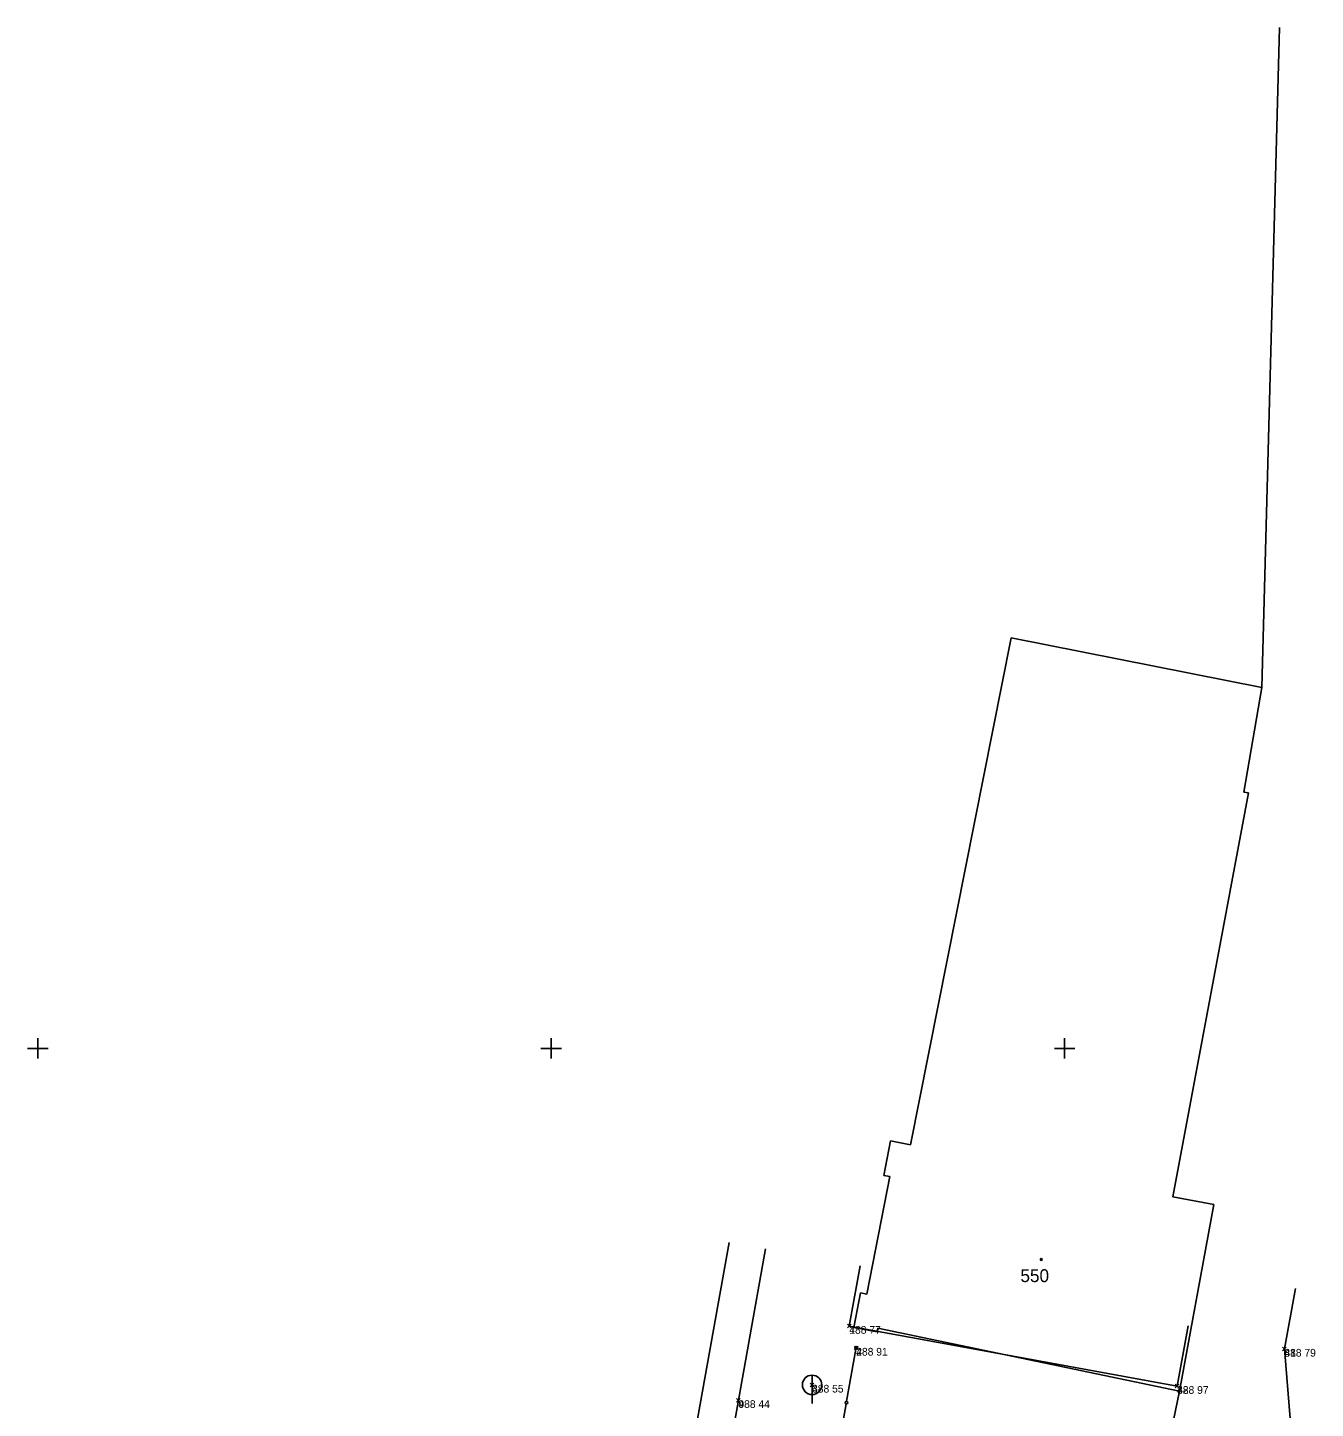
# Model space of a CAD drawing. Extents: x -866624 to -866276, y -1050208 to -1049940.
# Drawn here: x -866500.4 to -866450.2, y -1049994 to -1049940.2 of the extents above; entities that cross this region are included whole.
import ezdxf

# ---------------------------------------------------------------- set-up
doc = ezdxf.new("R2010")
doc.units = 0
for name, color, linetype in [('00_POMOCNÉ KCE', 7, 'Continuous'), ('bod-cislo', 7, 'Continuous'), ('bod-oznac', 7, 'Continuous'), ('bod-vyska', 7, 'Continuous'), ('BUDOVY', 7, 'Continuous'), ('CTV-SIT', 7, 'Continuous'), ('Default', 7, 'Continuous'), ('HRAN-LIN', 7, 'Continuous'), ('Hranice', 7, 'Continuous'), ('Hranice-budov', 7, 'Continuous'), ('KOLEJ', 7, 'Continuous'), ('Parcela-stavebni', 7, 'Continuous'), ('POTR-ZAR', 7, 'Continuous'), ('ZABRADLI', 7, 'Continuous'), ('znacky-budov', 7, 'Continuous')]:
    doc.layers.add(name, color=color, linetype=linetype)

# ---------------------------------------------------------------- blocks, each defined once
blk = doc.blocks.new('s_zdena')
at = {"layer": 'Default'}
blk.add_circle((0, 0), 0.175, dxfattribs=at)
for start, end in [(0, 180), (180, 0)]:
    blk.add_arc((0, 0), 0.0875, start, end, dxfattribs=at)
blk = doc.blocks.new('POINT_DISPLAY')
at = {"layer": 'Default'}
for p, q in [((-0.071, 0.071), (0.071, -0.071)), ((0.071, 0.071), (-0.071, -0.071))]:
    blk.add_line(p, q, dxfattribs=at)
blk = doc.blocks.new('200RS')
at = {"layer": 'POTR-ZAR'}
blk.add_line((0, -0.378), (0, 0.721), dxfattribs=at)
blk.add_circle((0, 0), 0.378, dxfattribs=at)
blk = doc.blocks.new('CTVSIT')
at = {"layer": 'Default'}
for p, q in [((-2, 0), (2, 0)), ((0, 2), (0, -2))]:
    blk.add_line(p, q, dxfattribs=at)
blk = doc.blocks.new('vytyčení')
at = {"layer": '00_POMOCNÉ KCE'}
blk.add_lwpolyline([(-866088.569, -1050068.4), (-866082.964, -1050067.078), (-866067.63, -1050067.491)], dxfattribs=at)

msp = doc.modelspace()

# ---------------------------------------------------------------- linework, layer by layer
at = {"layer": 'BUDOVY'}
for p, q in [((-866468.39, -1049990.82), (-866467.96, -1049988.472)), ((-866468.39, -1049990.82), (-866455.62, -1049993.16)), ((-866455.62, -1049993.16), (-866455.19, -1049990.812))]:
    msp.add_line(p, q, dxfattribs=at)
at = {"layer": 'HRAN-LIN'}
msp.add_line((-866451.44, -1049991.71), (-866451.01, -1049989.362), dxfattribs=at)
msp.add_lwpolyline([(-866451.44, -1049991.71), (-866450.97, -1049997.45), (-866453.67, -1050012.55)], dxfattribs=at)
at = {"layer": 'Hranice'}
for p, q in [((-866452.32, -1049965.94), (-866451.629, -1049940.226)), ((-866466.01, -1049983.76), (-866462.08, -1049964)), ((-866462.08, -1049964), (-866452.32, -1049965.94)), ((-866452.32, -1049965.94), (-866453.02, -1049970.01)), ((-866455.78, -1049985.79), (-866452.84, -1049970.04)), ((-866453.02, -1049970.01), (-866452.84, -1049970.04)), ((-866467.05, -1049984.95), (-866466.79, -1049983.6)), ((-866466.79, -1049983.6), (-866466.01, -1049983.76)), ((-866467.7, -1049989.58), (-866466.81, -1049984.99)), ((-866466.81, -1049984.99), (-866467.05, -1049984.95)), ((-866454.19, -1049986.08), (-866455.78, -1049985.79)), ((-866454.19, -1049986.08), (-866455.52, -1049993.35)), ((-866468.21, -1049990.88), (-866467.95, -1049989.53)), ((-866467.95, -1049989.53), (-866467.7, -1049989.58)), ((-866467.31, -1049991.05), (-866468.21, -1049990.88)), ((-866467.28, -1049990.9), (-866467.31, -1049991.05)), ((-866455.52, -1049993.35), (-866467.28, -1049990.9)), ((-866455.52, -1049993.35), (-866456.72, -1049999.15))]:
    msp.add_line(p, q, dxfattribs=at)
at = {"layer": 'Hranice-budov'}
for p, q in [((-866466.01, -1049983.76), (-866462.08, -1049964)), ((-866462.08, -1049964), (-866452.32, -1049965.94)), ((-866452.32, -1049965.94), (-866453.02, -1049970.01)), ((-866455.78, -1049985.79), (-866452.84, -1049970.04)), ((-866453.02, -1049970.01), (-866452.84, -1049970.04)), ((-866467.05, -1049984.95), (-866466.79, -1049983.6)), ((-866466.79, -1049983.6), (-866466.01, -1049983.76)), ((-866467.7, -1049989.58), (-866466.81, -1049984.99)), ((-866466.81, -1049984.99), (-866467.05, -1049984.95)), ((-866454.19, -1049986.08), (-866455.78, -1049985.79)), ((-866454.19, -1049986.08), (-866455.52, -1049993.35)), ((-866468.21, -1049990.88), (-866467.95, -1049989.53)), ((-866467.95, -1049989.53), (-866467.7, -1049989.58)), ((-866467.31, -1049991.05), (-866468.21, -1049990.88)), ((-866467.28, -1049990.9), (-866467.31, -1049991.05)), ((-866455.52, -1049993.35), (-866467.28, -1049990.9))]:
    msp.add_line(p, q, dxfattribs=at)
at = {"layer": 'KOLEJ'}
for p, q in [((-866473.069, -1049987.559), (-866486.976, -1050065.382)), ((-866471.656, -1049987.812), (-866485.563, -1050065.635))]:
    msp.add_line(p, q, dxfattribs=at)
at = {"layer": 'ZABRADLI'}
for p, q in [((-866468.129, -1049991.719), (-866468.493, -1049993.752)), ((-866468.51, -1049993.85), (-866468.874, -1049995.883))]:
    msp.add_line(p, q, dxfattribs=at)
for centre in [(-866468.12, -1049991.67), (-866468.501, -1049993.801)]:
    msp.add_circle(centre, 0.05, dxfattribs=at)

# ---------------------------------------------------------------- block references
at = {"layer": '00_POMOCNÉ KCE', "rotation": -98.59344504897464}
msp.add_blockref('vytyčení', (42415.469, -2063260.675), dxfattribs=at)
at = {"layer": 'bod-oznac'}
for p in [(-866468.39, -1049990.82), (-866468.12, -1049991.67), (-866451.44, -1049991.71), (-866469.84, -1049993.11), (-866455.62, -1049993.16), (-866472.71, -1049993.71)]:
    msp.add_blockref('POINT_DISPLAY', p, dxfattribs=at)
at = {"layer": 'CTV-SIT', "xscale": 0.19999999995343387, "yscale": 0.19999999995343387}
for p in [(-866500, -1049980), (-866480, -1049980), (-866460, -1049980)]:
    msp.add_blockref('CTVSIT', p, dxfattribs=at)
at = {"layer": 'POTR-ZAR', "rotation": 179.99999999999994}
msp.add_blockref('200RS', (-866469.84, -1049993.11), dxfattribs=at)
at = {"layer": 'znacky-budov', "xscale": 0.2, "yscale": 0.20000000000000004}
msp.add_blockref('s_zdena', (-866460.912, -1049988.225), dxfattribs=at)

# ---------------------------------------------------------------- texts
at = {"layer": 'bod-cislo'}
for s, p in [('1', (-866468.39, -1049991.12)), ('2', (-866468.12, -1049991.97)), ('81', (-866451.44, -1049992.01)), ('3', (-866469.84, -1049993.41)), ('82', (-866455.62, -1049993.46)), ('9', (-866472.71, -1049994.01))]:
    msp.add_text(s, height=0.3, dxfattribs=at).set_placement(p)
at = {"layer": 'bod-vyska'}
for s, p in [('488 77', (-866468.39, -1049991.12)), ('488 91', (-866468.12, -1049991.97)), ('488 79', (-866451.44, -1049992.01)), ('488 55', (-866469.84, -1049993.41)), ('488 97', (-866455.62, -1049993.46)), ('488 44', (-866472.71, -1049994.01))]:
    msp.add_text(s, height=0.3, dxfattribs=at).set_placement(p)
at = {"layer": 'Parcela-stavebni'}
msp.add_text('550', height=0.5, dxfattribs=at).set_placement((-866461.723, -1049989.106))

doc.saveas('drawing.dxf')
